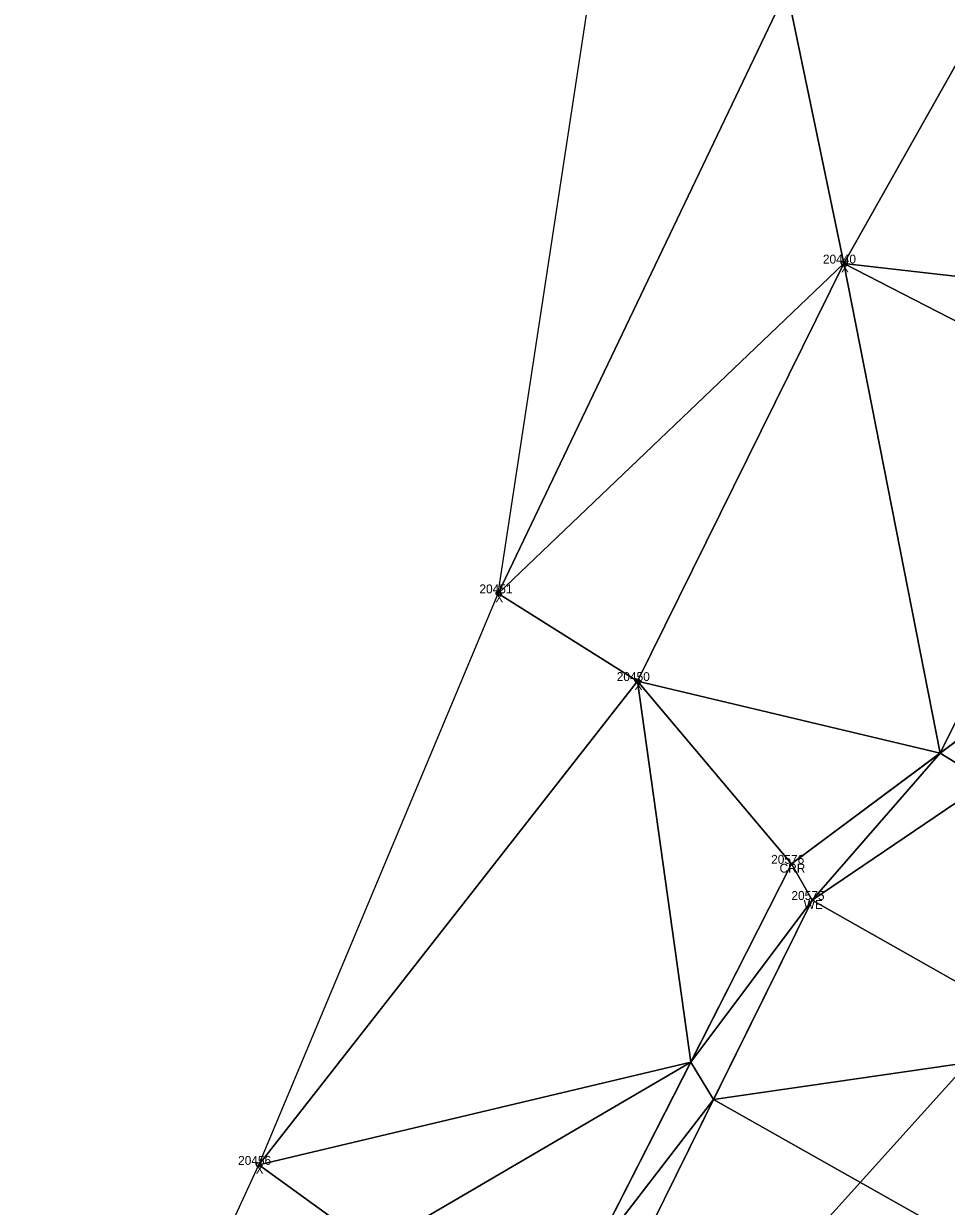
# Model space of a CAD drawing. Extents: x 1966740 to 1969291, y 1117379 to 1118460.
# Drawn here: x 1967761.2 to 1967864.9, y 1118100.7 to 1118233.7 of the extents above; entities that cross this region are included whole.
import ezdxf

# ---------------------------------------------------------------- set-up
doc = ezdxf.new("R2010")
doc.units = 0
for name, color, linetype in [('Level 1', 7, 'Continuous'), ('Level 10', 7, 'Continuous'), ('Level 30', 7, 'Continuous'), ('Level 35', 7, 'Continuous'), ('Level 50', 7, 'Continuous'), ('Level 52', 7, 'Continuous'), ('Level 60', 7, 'Continuous'), ('Level 61', 7, 'Continuous'), ('Level 62', 7, 'Continuous')]:
    doc.layers.add(name, color=color, linetype=linetype)

msp = doc.modelspace()

# ---------------------------------------------------------------- linework, layer by layer
at = {"layer": 'Level 1'}
msp.add_line((1967931.05, 1118187.54), (1967834.04, 1118079.96), dxfattribs=at)
at = {"layer": 'Level 10'}
for points in [[(1967848.72, 1118350.07), (1967881.79, 1118342.06), (1967895.58, 1118338.92), (1967907.43, 1118282.36), (1967910.66, 1118232.56), (1967917.99, 1118192.64), (1967910.91, 1118176.45), (1967849.83, 1118135.18), (1967825.91, 1118086.77)], [(1967848.54, 1118347.45), (1967880.38, 1118337.78), (1967886.93, 1118331.58), (1967896.4, 1118282.85), (1967906.33, 1118232.39), (1967914.38, 1118193.81), (1967904.29, 1118181.59), (1967847.52, 1118139.25), (1967823.99, 1118093.05), (1967800.15, 1118046.69), (1967791.83, 1117992.41), (1967789.93, 1117935.61), (1967798.32, 1117889.19), (1967796.67, 1117880.97)]]:
    msp.add_lwpolyline(points, dxfattribs=at)
at = {"layer": 'Level 30'}
for centre in [(1967853.4, 1118206.72), (1967814.56, 1118169.65), (1967830.21, 1118159.79), (1967787.64, 1118105.41)]:
    msp.add_circle(centre, 0.25, dxfattribs=at)
at = {"layer": 'Level 35'}
for points in [[(1967814.56, 1118169.65), (1967836.22, 1118311.82), (1967846.97, 1118237.53)], [(1967846.97, 1118237.53), (1967872.12, 1118239.98), (1967853.4, 1118206.72)], [(1967853.4, 1118206.72), (1967872.12, 1118239.98), (1967870.12, 1118204.81)], [(1967814.56, 1118169.65), (1967846.97, 1118237.53), (1967853.4, 1118206.72)], [(1967814.56, 1118169.65), (1967853.4, 1118206.72), (1967830.21, 1118159.79)], [(1967830.21, 1118159.79), (1967853.4, 1118206.72), (1967864.21, 1118151.69)], [(1967853.4, 1118206.72), (1967870.12, 1118204.81), (1967883.77, 1118191.11)], [(1967853.4, 1118206.72), (1967883.77, 1118191.11), (1967864.21, 1118151.69)], [(1967864.21, 1118151.69), (1967883.77, 1118191.11), (1967884.25, 1118166.64)], [(1967787.64, 1118105.41), (1967814.56, 1118169.65), (1967830.21, 1118159.79)], [(1967864.21, 1118151.69), (1967884.25, 1118166.64), (1967869.48, 1118148.46)], [(1967787.64, 1118105.41), (1967830.21, 1118159.79), (1967836.18, 1118116.97)], [(1967830.21, 1118159.79), (1967864.21, 1118151.69), (1967847.52, 1118139.25)], [(1967830.21, 1118159.79), (1967847.52, 1118139.25), (1967836.18, 1118116.97)], [(1967847.52, 1118139.25), (1967864.21, 1118151.69), (1967849.83, 1118135.18)], [(1967849.83, 1118135.18), (1967864.21, 1118151.69), (1967869.48, 1118148.46)], [(1967849.83, 1118135.18), (1967869.48, 1118148.46), (1967879.07, 1118118.61)], [(1967836.18, 1118116.97), (1967847.52, 1118139.25), (1967849.83, 1118135.18)], [(1967836.18, 1118116.97), (1967849.83, 1118135.18), (1967838.76, 1118112.77)], [(1967838.76, 1118112.77), (1967849.83, 1118135.18), (1967879.07, 1118118.61)], [(1967838.76, 1118112.77), (1967879.07, 1118118.61), (1967868.26, 1118096.07)], [(1967787.64, 1118105.41), (1967836.18, 1118116.97), (1967800.55, 1118096.07)], [(1967800.55, 1118096.07), (1967836.18, 1118116.97), (1967824.83, 1118094.7)], [(1967824.83, 1118094.7), (1967836.18, 1118116.97), (1967838.76, 1118112.77)], [(1967824.83, 1118094.7), (1967838.76, 1118112.77), (1967827.68, 1118090.36)], [(1967827.68, 1118090.36), (1967838.76, 1118112.77), (1967868.26, 1118096.07)], [(1967761.22, 1118047.98), (1967787.64, 1118105.41), (1967800.55, 1118096.07)]]:
    msp.add_lwpolyline(points, close=True, dxfattribs=at)
at = {"layer": 'Level 50'}
for centre in [(1967847.52, 1118139.25), (1967849.83, 1118135.18)]:
    msp.add_circle(centre, 0.001, dxfattribs=at)

# ---------------------------------------------------------------- texts
at = {"layer": 'Level 52'}
for s, p in [('20440', (1967851.04, 1118206.72)), ('20451', (1967812.44, 1118169.65)), ('20450', (1967827.87, 1118159.79)), ('20456', (1967785.32, 1118105.41))]:
    msp.add_text(s, height=1, dxfattribs=at).set_placement(p)
at = {"layer": 'Level 60'}
for s, p in [('CRR', (1967846.17, 1118138.25)), ('WE', (1967848.88, 1118134.18))]:
    msp.add_text(s, height=1, dxfattribs=at).set_placement(p)
at = {"layer": 'Level 61'}
for s, p in [('20576', (1967845.22, 1118139.25)), ('20575', (1967847.5, 1118135.18))]:
    msp.add_text(s, height=1, dxfattribs=at).set_placement(p)
at = {"layer": 'Level 62'}
for p in [(1967853.07, 1118205.72), (1967814.23, 1118168.65), (1967829.87, 1118158.79), (1967787.3, 1118104.41)]:
    msp.add_text('X', height=1, dxfattribs=at).set_placement(p)

doc.saveas('drawing.dxf')
